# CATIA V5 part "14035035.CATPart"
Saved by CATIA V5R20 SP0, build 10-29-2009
Part number: 14035035
Definition: NONE
Nomenclature: 14035035
Source: Unknown
Description: 14035035
Bounding box of the stored display mesh (mm): x -17.5 to 70, y -31.5 to 21.6, z -21.6 to 21.6
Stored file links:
  C:\Users\Utente\Desktop\IO LAVORO\3D X SITO CF\X SITO\PLASTICA\RF2\14035035.CATPart
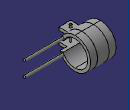
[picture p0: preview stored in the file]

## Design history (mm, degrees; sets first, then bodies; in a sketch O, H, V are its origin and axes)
Body1 "14035035" (main body)
  Solid1: solid without history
